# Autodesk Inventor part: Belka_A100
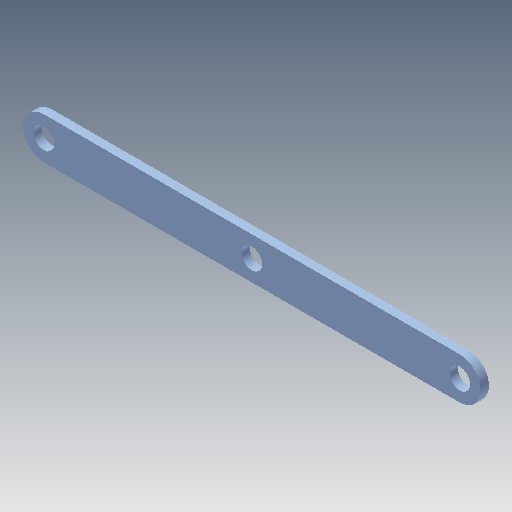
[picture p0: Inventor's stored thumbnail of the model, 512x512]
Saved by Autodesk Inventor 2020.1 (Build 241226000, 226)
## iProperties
Created: 2006-06
Part Number: Belka_A100
Document SubType Name: Modeling
Designer: F.Stasiak
Density: 1 g/cm^3
Material: Ogólny
Appearance: Niebieski pastelowy
Manager: www.cadconsulting.pl
Company: Fabian Stasiak CAD Consulting
Author: F.Stasiak
Subject: Zbiór ćwiczeń. Autodesk Inventor 2020. Kurs podstawowy
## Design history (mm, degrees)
sketch "Szkic1"
  geometry: L1 (0, 50)-(1000, 50); L2 (1000, -50)-(0, -50); L3 (0, 0)-(1000, 0); C1 r 25 at (0, 0); C2 r 25 at (1000, 0); C3 r 25 at (500, 0); A1 r 50 centre (1000, 0) between (1000, -50) and (1000, 50); A2 r 50 centre (0, 0) between (0, 50) and (0, -50); 1 further point
  constraints: 6 end point, 5 centre point, 4 point on circle, 4 tangent, 3 coincident, 2 equal radius, 2 parallel, 1 horizontal, 1 midpoint
  dimensions: "d0" = 50 radius of A2; "d1" = 1000 distance of L2.start L2.end; "d2" = 50 diameter of C1 (= d0)
extrude "Wyciągnięcie proste1" new body sketch "Szkic1" stored distance "d3" = 20; taper "d4" = 0 deg
node "Bryła1"
node "Korpusy bryłowe"
node "Korpusy powierzchniowe"
